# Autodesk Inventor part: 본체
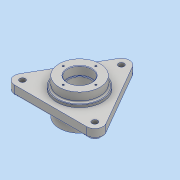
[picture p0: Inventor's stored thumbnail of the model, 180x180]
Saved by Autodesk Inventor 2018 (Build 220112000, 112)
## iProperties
Created: 2023-04
Part Number: 본체
Material: 알루미늄 6061
Document SubType Name: Modeling
Designer: 강의실04
Density: 2.7 g/cm^3
Appearance: 알루미늄 - 평지
Mass: 1216.58 g
Surface Area: 638.354 cm^2
Volume: 450.586 cm^3
Author: 강의실04
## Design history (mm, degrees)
sketch "스케치1"
  geometry: L1 (-13.856, 90)-(-84.87, -33); L2 (-71.014, -57)-(71.014, -57); L3 (84.87, -33)-(13.856, 90); A1 r 16 centre (0, 82) between (13.856, 90) and (-13.856, 90); A2 r 16 centre (-71.014, -41) between (-84.87, -33) and (-71.014, -57); A3 r 16 centre (71.014, -41) between (71.014, -57) and (84.87, -33); 2 further points
  constraints: 6 end point, 6 point on circle, 6 tangent, 3 centre point, 2 equal radius, 1 coincident, 1 horizontal
  dimensions: "d11" = 60 deg angle of L3 L1; "d12" = 60 deg angle of L2 L1; "d13" = 16 radius of A1 (derived)
extrude "돌출1" new body sketch "스케치1" distance "d14" = 18; taper "d15" = 0 deg
sketch "스케치3"
  geometry: C1 r 45 at (0, 0); C2 r 40 at (0, 0); 1 further point
  constraints: 2 centre point, 2 coincident
  dimensions: "d22" = 90 diameter of C1; "d23" = 80 diameter of C2
extrude "돌출3" join sketch "스케치3" distance "d24" = 5; taper "d25" = 0 deg
sketch "스케치4"
  geometry: L1 (13.856, 90)-(84.87, -33) reference; L2 (71.014, -57)-(-71.014, -57) reference; L3 (-84.87, -33)-(-13.856, 90) reference; C1 r 40 at (0, 0) reference; C2 r 45 at (0, 0) reference; A1 r 16 centre (0, 82) between (13.856, 90) and (-13.856, 90) reference; A2 r 16 centre (71.014, -41) between (71.014, -57) and (84.87, -33) reference; A3 r 16 centre (-71.014, -41) between (-84.87, -33) and (-71.014, -57) reference; 1 further point
extrude "돌출4" join sketch "스케치4" distance "d26" = 23; taper "d27" = 0 deg
sketch "스케치5"
  geometry: C1 r 40 at (0, 0); 1 further point
  constraints: 1 centre point, 1 coincident
  dimensions: "d28" = 80 diameter of C1
extrude "돌출5" join sketch "스케치5" distance "d29" = 29; taper "d30" = 0 deg
hole "구멍1" diameter "d33" = 42; stored, may be unused: countersink angle "d37" = 90 deg, drill point angle "d39" = 118 deg; dims "d31" = 10, "d32" = 10, "d34" = 6, "d35" = 47, "d36" = 17, "d38" = 8
hole "구멍2" diameter "d42" = 42; stored, may be unused: countersink angle "d46" = 90 deg, drill point angle "d48" = 118 deg; dims "d40" = 10, "d41" = 10, "d43" = 6, "d44" = 47, "d45" = 17, "d47" = 8
sketch "스케치6"
  geometry: L1 (13.856, 90)-(84.87, -33) reference; L2 (71.014, -57)-(-71.014, -57) reference; L3 (-84.87, -33)-(-13.856, 90) reference; C1 r 21 at (0, 0) reference; C2 r 40 at (0, 0) reference; C3 r 11 at (0, 82); C4 r 11 at (-71.014, -41); C5 r 11 at (71.014, -41); A1 r 16 centre (0, 82) between (13.856, 90) and (-13.856, 90) reference; A2 r 16 centre (71.014, -41) between (71.014, -57) and (84.87, -33) reference; A3 r 16 centre (-71.014, -41) between (-84.87, -33) and (-71.014, -57) reference; 1 further point
  constraints: 3 centre point, 2 coincident
  dimensions: "d49" = 22 diameter of C3; "d50" = 22 diameter of C4; "d51" = 22 diameter of C5
  node "절단 모서리 투영3"
sketch "스케치7"
  geometry: L1 (13.856, 90)-(84.87, -33) reference; L2 (71.014, -57)-(-71.014, -57) reference; L3 (-84.87, -33)-(-13.856, 90) reference; C1 r 21 at (0, 0) reference; C2 r 45 at (0, 0) reference; A1 r 16 centre (0, 82) between (13.856, 90) and (-13.856, 90) reference; A2 r 16 centre (71.014, -41) between (71.014, -57) and (84.87, -33) reference; A3 r 16 centre (-71.014, -41) between (-84.87, -33) and (-71.014, -57) reference; 1 further point
hole "구멍3" sketch "스케치7" at (0, 82), (-71.014, -41), (71.014, -41) diameter "d54" = 11; stored, may be unused: countersink angle "d58" = 90 deg, drill point angle "d60" = 118 deg; dims "d55" = 6, "d56" = 47, "d57" = 17, "d59" = 8
fillet "모깎기2" dims "d62" = 3
fillet "모깎기3" dims "d63" = 3
sketch "스케치8" dims "d65" = 64
  geometry: C1 r 40 at (0, 0) reference; C2 r 23.5 at (0, 0) reference; 3 further points
  constraints: 1 coincident, 1 vertical alignment, 2 other
hole "구멍4" sketch "스케치8" at (0, 32) diameter "d66" = 3.459; stored, may be unused: countersink angle "d70" = 90 deg, drill point angle "d72" = 118 deg; dims "d67" = 8, "d68" = 47, "d69" = 17, "d71" = 10
node "작업 평면1"
sketch "스케치9"
  geometry: L1 (13.856, 90)-(84.87, -33) reference; L2 (71.014, -57)-(-71.014, -57) reference; L3 (-84.87, -33)-(-13.856, 90) reference; C1 r 43 at (0, 0) reference; C2 r 5.5 at (71.014, -41) reference; C3 r 5.5 at (0, 82) reference; C4 r 5.5 at (-71.014, -41) reference; C5 r 21 at (0, 0) reference; A1 r 16 centre (0, 82) between (13.856, 90) and (-13.856, 90) reference; A2 r 16 centre (71.014, -41) between (71.014, -57) and (84.87, -33) reference; A3 r 16 centre (-71.014, -41) between (-84.87, -33) and (-71.014, -57) reference; 1 further point
  node "절단 모서리 투영6"
extrude "돌출7" join sketch "스케치6" distance "d76" = 3; taper "d77" = 0 deg
sketch "스케치10"
  geometry: L1 (13.856, 90)-(84.87, -33) reference; L2 (71.014, -57)-(-71.014, -57) reference; L3 (-84.87, -33)-(-13.856, 90) reference; C1 r 11 at (-71.014, -41) reference; C2 r 11 at (0, 82) reference; C3 r 11 at (71.014, -41) reference; C4 r 43 at (0, 0) reference; C5 r 5.5 at (71.014, -41) reference; C6 r 5.5 at (0, 82) reference; C7 r 5.5 at (-71.014, -41) reference; C8 r 21 at (0, 0) reference; C9 r 5.5 at (0, 82); C10 r 5.5 at (-71.014, -41); C11 r 5.5 at (71.014, -41); A1 r 16 centre (0, 82) between (13.856, 90) and (-13.856, 90) reference; A2 r 16 centre (71.014, -41) between (71.014, -57) and (84.87, -33) reference; A3 r 16 centre (-71.014, -41) between (-84.87, -33) and (-71.014, -57) reference; 1 further point
  constraints: 3 centre point, 2 coincident
  dimensions: "d78" = 11 diameter of C9; "d79" = 11 diameter of C10; "d80" = 11 diameter of C11
extrude "돌출8" cut sketch "스케치10" distance "d81" = 5; taper "d82" = 0 deg
fillet "모깎기5" dims "d83" = 0.6
sketch "스케치11"
  geometry: 2 further points
  constraints: 1 other
  dimensions: "d84" = 60 vertical distance of point (0, 0) point (0.303, 60)
feature "엠보싱1" sketch "스케치11" dims "d11" = 60 deg, "d12" = 60 deg, "d13" = 16 (derived), "d27" = 0, "d85" = 0.5, "d86" = 0
fillet "모깎기8" dims "d89" = 3
fillet "모깎기9" dims "d90" = 3
chamfer "모따기1" distance "d91" = 1; stored, may be unused: second distance "d92" = 2, angle "d93" = 45 deg
node "솔리드1"
pattern_circular "원형 패턴1" dims angle "d74" = 360 deg
mirror "미러1"
node "절단 모서리 투영2"
node "절단 모서리 투영4"
node "절단 모서리 투영5"
node "절단 모서리 투영7"
